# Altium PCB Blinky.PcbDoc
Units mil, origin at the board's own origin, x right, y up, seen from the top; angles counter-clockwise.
Board outline 1000 x 1000 mil, 2 copper layers (Top Layer, Bottom Layer); 10 components, 6 nets, 23 pads, 0 vias.
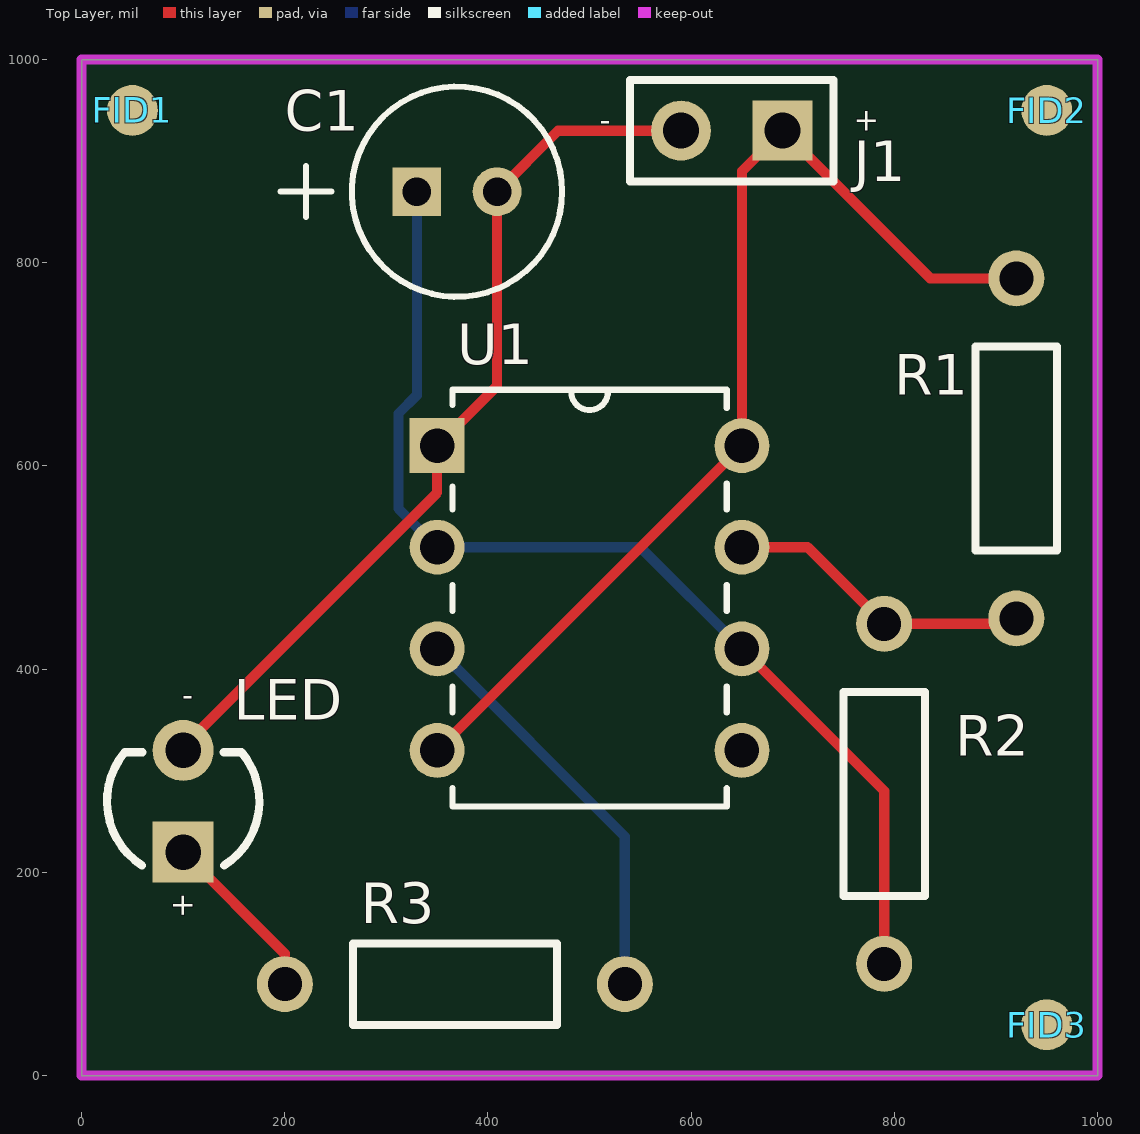
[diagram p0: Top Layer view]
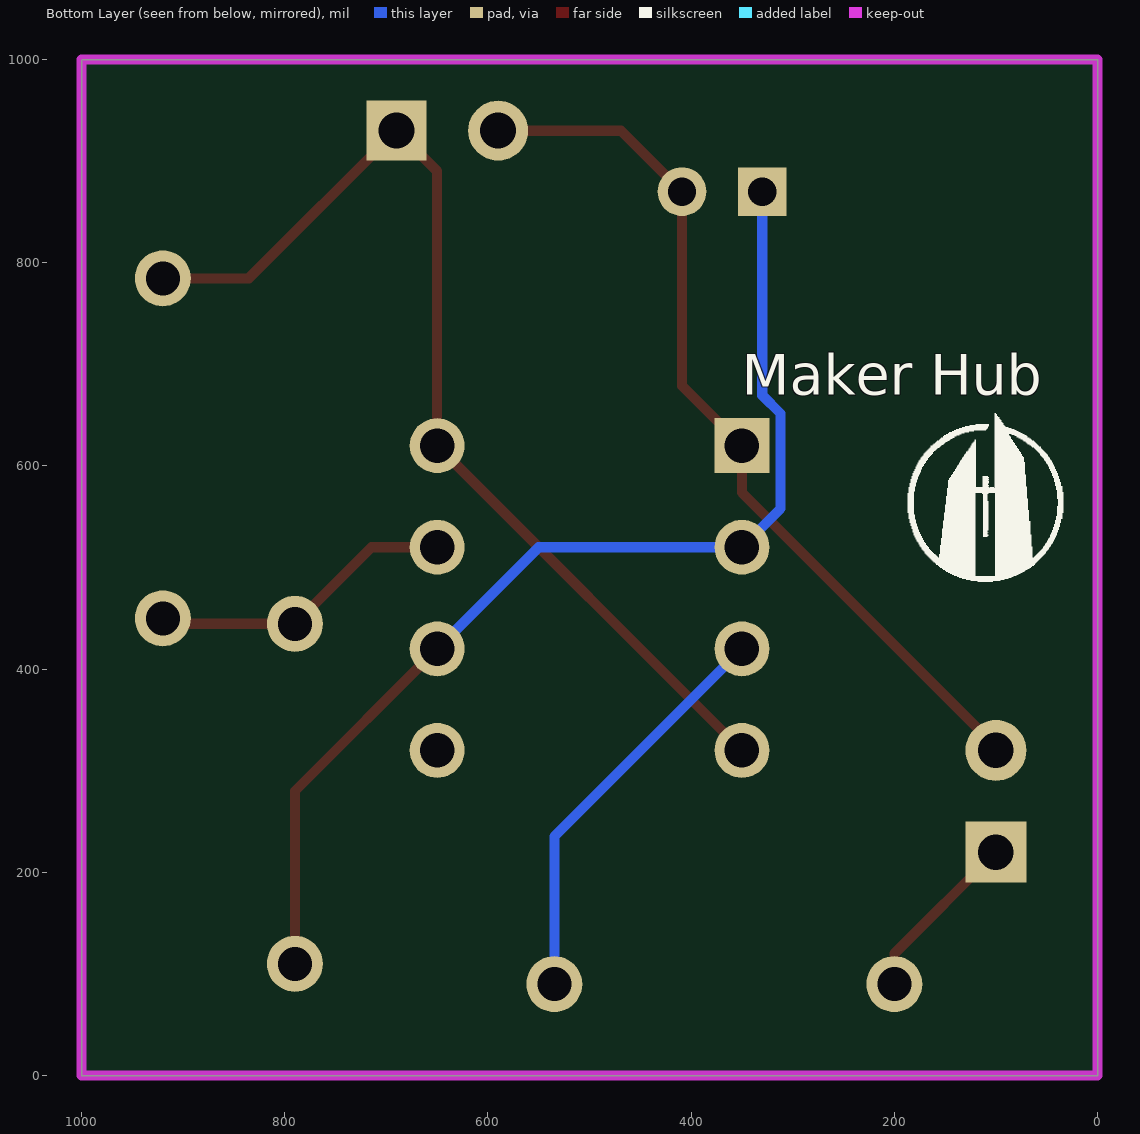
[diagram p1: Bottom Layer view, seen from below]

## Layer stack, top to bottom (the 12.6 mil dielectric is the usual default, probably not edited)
Top Solder: solder mask 0.4, Solder Resist, Dk 3.5
Top Layer: signal copper 1.4
Dielectric 1: dielectric 12.6, FR-4, Dk 4.8
Bottom Layer: signal copper 1.4
Bottom Solder: solder mask 0.4, Solder Resist, Dk 3.5

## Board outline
0,0 0,1000 1000,1000 1000,0

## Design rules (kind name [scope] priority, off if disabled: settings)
BoardOutlineClearance [All] p1: gap=15 ignorepadtopadclearanceinfootprint=FALSE
Clearance [All] p1: gap=6 ignorepadtopadclearanceinfootprint=FALSE except(0: Arc-Hole Track-Hole SMDPad-Hole THPad-Hole Via-Hole Fill-Hole Poly-Hole Region-Hole Text-Hole)
Clearance "Clearance~Sunstone Circuits" [All] p2: gap=6 ignorepadtopadclearanceinfootprint=FALSE except(0: Arc-Hole Track-Hole SMDPad-Hole THPad-Hole Via-Hole Fill-Hole Poly-Hole Region-Hole Text-Hole) // Sunstone Circuits Minimum Clearance Rule (Double Sided)
ComponentClearance [All] p1: gap=1 collisioncheckmode=3 verticalgap=1 showdistances=FALSE
DiffPairsRouting [All] p1: maxlimit=393.7 minlimit=6 mostfreqgap=8 toplayer_minwidth=6 toplayer_maxwidth=15 toplayer_prefwidth=8 bottomlayer_minwidth=6 bottomlayer_maxwidth=15 bottomlayer_prefwidth=8 maxuncoupledlength=500
HoleSize [All] p1: absolutevalues=TRUE maxlimit=265 minlimit=13 maxpercent=80.000 minpercent=20.000
HoleSize "HoleSize~Sunstone Circuits" [All] p2: absolutevalues=TRUE maxlimit=251 minlimit=16 maxpercent=80.000 minpercent=20.000 // SSC Hole Size Rule For Single Sided & Double Sided Designs.
HoleSize Testpoint [All] p3: absolutevalues=TRUE maxlimit=100 minlimit=1 maxpercent=80.000 minpercent=20.000
HoleSize TestPointUsage [All] p4: absolutevalues=TRUE maxlimit=100 minlimit=1 maxpercent=80.000 minpercent=20.000
HoleToHoleClearance [All] p1: gap=10 allowstackedmicrovias=FALSE
MinimumAnnularRing [All] p1: minimumring=7
MinimumAnnularRing "MinimumAnnularRing~Sunstone Circuits" [All] p2: minimumring=7 // Sunstone Circuits Minimum Annular Ring (Double Sided)
MinimumSolderMaskSliver [All] p1: minsoldermaskwidth=0
PlaneClearance [All] p1: clearance=10
PlaneClearance "PlaneClearance~Sunstone Circuits" [All] p2: clearance=12 // Sunstone Circuits Power Plane Clearance Rule (Double Sided)
PlaneConnect [All] p1: planeconnectstyle=Direct reliefexpansion=16 reliefentries=4 reliefconductorwidth=6 reliefairgap=6
PlaneConnect "PlaneConnect~Sunstone Circuits" [All] p2: planeconnectstyle=Relief reliefexpansion=10 reliefentries=4 reliefconductorwidth=8 reliefairgap=10 // Sunstone Circuits Power Plane Connect Rule (Double Sided)
PolygonConnect [All] p1: connectstyle=Relief reliefconductorwidth=8 reliefentries=4 polygonreliefangle="90 Angle" airgapwidth=6
PolygonConnect "PolygonConnect~Sunstone Circuits" [All] p2: connectstyle=Relief reliefconductorwidth=8 reliefentries=4 polygonreliefangle="90 Angle" airgapwidth=10 // Sunstone Circuits Polygon Connect Style (Double Sided)
RoutingCorners [All] p1: cornerstyle=45-Degree minsetback=49.21 maxsetback=49.21
RoutingVias [All] p1: holewidth=15 width=30 viastyle="Through Hole" minholewidth=13 minwidth=27 maxholewidth=100 maxwidth=114
RoutingVias "RoutingVias~Sunstone Circuits" [All] p2: holewidth=16 width=30 viastyle="Through Hole" minholewidth=16 minwidth=30 maxholewidth=20 maxwidth=40 // Sunstone Circuits Routing Vias Rule (Double Sided)
ShortCircuit "ShortCircuit~Sunstone Circuits" [All] p2: allowed=FALSE // Sunstone Circuits Short Circuit Rule~Do Not Allow (Double Sided)
SilkToSilkClearance [All] p1: silktosilkclearance=0
SilkToSolderMaskClearance [IsPad] p1: minsilkscreentomaskgap=6 clearancetoexposedcopper=TRUE
SolderMaskExpansion [All] p1: expansion=2.95
SolderMaskExpansion "SolderMaskExpansion~Sunstone Circuits" [All] p2: expansion=3 // Sunstone Circuits Solder Mask Expansion Rule (Double Sided)
ViasUnderSMD "ViasUnderSMD~Sunstone Circuits" [All] p1: allowed=FALSE // Sunstone Circuits Vias Under SMD~Do Not Allow (Double Sided)
Width [All] p1: maxlimit=400 minlimit=6 preferedwidth=8
Width "Width~Sunstone Circuits" [All] p2: maxlimit=100 minlimit=6 preferedwidth=10 // Sunstone Circuits Minimum Width Rule (Double Sided)
20 further rules are at their usual default settings.

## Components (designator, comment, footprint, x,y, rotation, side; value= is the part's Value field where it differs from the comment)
C1 "1 uF, 50V, 20%" U1-E 409,870 r0 top value=Value
FID1 "Fiducial Marker" FIDUCIAL2 50,950 r90 top
FID2 "Fiducial Marker" FIDUCIAL2 950,950 r90 top
FID3 "Fiducial Marker" FIDUCIAL2 950,50 r90 top
J1 "2-pin Header" EMPTY_HDR2X1 590,930 r270 top
LED "4mm Red LED" 3MM_THRU-HOLE_LED 100,220 r90 top
R1 "1 kOhm, through-hole" RES_THRU_HOLE 920,450 r90 top
R2 "470 kOhm, through-hole" RES_THRU_HOLE 790,110 r90 top
R3 "1 kOhm, through-hole" RES_THRU_HOLE 200,90 r0 top
U1 "NE555P" NE555P 650,320 r0 top value=Value

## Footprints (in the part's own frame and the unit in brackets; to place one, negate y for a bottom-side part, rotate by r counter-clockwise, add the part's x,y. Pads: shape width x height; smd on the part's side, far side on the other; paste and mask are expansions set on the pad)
3MM_THRU-HOLE_LED [mil]
  rect 60x60 hole 35: 1(0,0)
  round 60 hole 35: 2(100,0)
  silkscreen extent -13,-75 98,75, body extent -15,-65 115,65, height 205
EMPTY_HDR2X1 [mm]
  rect 1.5x1.5 hole 0.9: 1(0,2.54)
  round 1.5 hole 0.9: 2(0,0)
  silkscreen extent -1.27,-1.27 1.27,3.81
FIDUCIAL2 [mil] "Fiducial marker"
  round 50 smd: FID(0,0)
NE555P [mil]
  rect 54x54 / inner round 60 / far side rect 54x54 hole 34 paste+0 mask+0: 1(-300,300)
  round 54 / inner round 60 / far side round 54 hole 34 paste+0 mask+0: 2(-300,200) 3(-300,100) 4(-300,0) 5(0,0) 6(0,100) 7(0,200) 8(0,300)
  silkscreen extent -285,-55 -15,355, body extent -310,-50 10,350, height 210
RES_THRU_HOLE [mm]
  round 1.4 hole 0.85: 1(0,0) 2(8.5,0)
  silkscreen extent 1.7,-1.02 6.8,1.02
U1-E [mil]
  rect 48x48 / inner round 60 / far side rect 48x48 hole 28 paste+0: 1(-79,0)
  round 48 / inner round 60 / far side round 48 hole 28 paste+0: 2(0,0)
  silkscreen extent -213,-103 64,103, body extent -138,-98 59,98, height 428

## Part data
C1: library part UVP1H010MDD1TD, "1 uF, 50V, 20% Capacitor", Supplier Part Number 1=493-12697-1-ND
FID1 FID2 FID3: library part FIDUCIAL_2
J1: library part Empty_Header_2x1, "Header, 2 pin"
LED: library part LTL-4222N, "LED 3MM HI-EFF RED TRANSPARENT", Manufacturer 1=Lite-On, Supplier Part Number 1=160-1140-ND
R1 R3: library part Resistors_1k, "Resistor"
R2: library part Resistors_470k, "Resistor"
U1: "NE555P Timer", Supplier Part Number 1=296-1411-5-ND

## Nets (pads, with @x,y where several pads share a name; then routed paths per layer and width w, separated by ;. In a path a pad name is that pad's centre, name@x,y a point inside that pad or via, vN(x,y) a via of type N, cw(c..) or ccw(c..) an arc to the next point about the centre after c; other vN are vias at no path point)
GND: C1.2 J1.2 LED.2 U1.1 | length 883.8
  Top Layer w10: LED.2 100,323.74 350,573.74 U1.1 409,679 C1.2 469,930 J1.2
NetC1_1: C1.1 R2.1 U1.2 U1.6 | length 1082.6
  Top Layer w10: U1.6 790,280 R2.1
  Bottom Layer w10: C1.1 330,669.56 312,651.56 312,558 U1.2 550,520 U1.6
NetLED_1: LED.1 R3.1 | length 171.4
  Top Layer w10: LED.1 200,120 R3.1
NetR1_1: R1.1 R2.2 U1.7 | length 303.4
  Top Layer w10: U1.7 714.65,520 R2.2 914.65,444.65 R1.1
NetR3_2: R3.2 U1.3 | length 406.5
  Bottom Layer w10: U1.3 534.65,235.35 R3.2
VCC: J1.1 R1.2 U1.4 U1.8 | length 1041
  Top Layer w10: U1.4 U1.8 650,890 J1.1 835.35,784.65 R1.2
pads on no net: FID1.FID FID2.FID FID3.FID U1.5

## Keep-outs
Keep-Out Layer:
  the board outline again, w10

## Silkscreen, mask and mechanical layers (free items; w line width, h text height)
Top Overlay:
  text "-" at 510,930 h22
  text "+" at 760,930 h22
  text "-" at 110,380 h22 r180
  text "+" at 90,180 h22 r270
Bottom Overlay:
  region: 1024 vertices and 2 holes, not listed, extent 34,486 187,652
  text "Maker Hub" at 350,670 h40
